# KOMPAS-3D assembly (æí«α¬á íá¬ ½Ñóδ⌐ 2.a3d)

Referenced files in D:\АСКОН работа\Конкурс HOME\06_Сюваев_Сборная модель танка Т90\ДЕТАЛИ\КОРПУС\МЕТАЛЛ\КОРПУС ШТАМПОВКА\БАКИ\: бак левый 2.m3d
Referenced files in D:\АСКОН работа\Конкурс HOME\06_Сюваев_Сборная модель танка Т90\ДЕТАЛИ\ОБЩИЕ ДЕТАЛИ\: шарниры ящиков.m3d, замки ящиков.m3d
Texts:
  Сборка бак левый 2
